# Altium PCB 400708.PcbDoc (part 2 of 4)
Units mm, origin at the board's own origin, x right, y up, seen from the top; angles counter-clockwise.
Board outline 117 x 63.5 mm, 4 copper layers (Top Layer, Mid-Layer 1, Mid-Layer 2, Bottom Layer), stack 1.556 mm thick; 207 components, 162 nets, 822 pads, 1266 vias.
Unrouted connection lines stored in the file: 43.
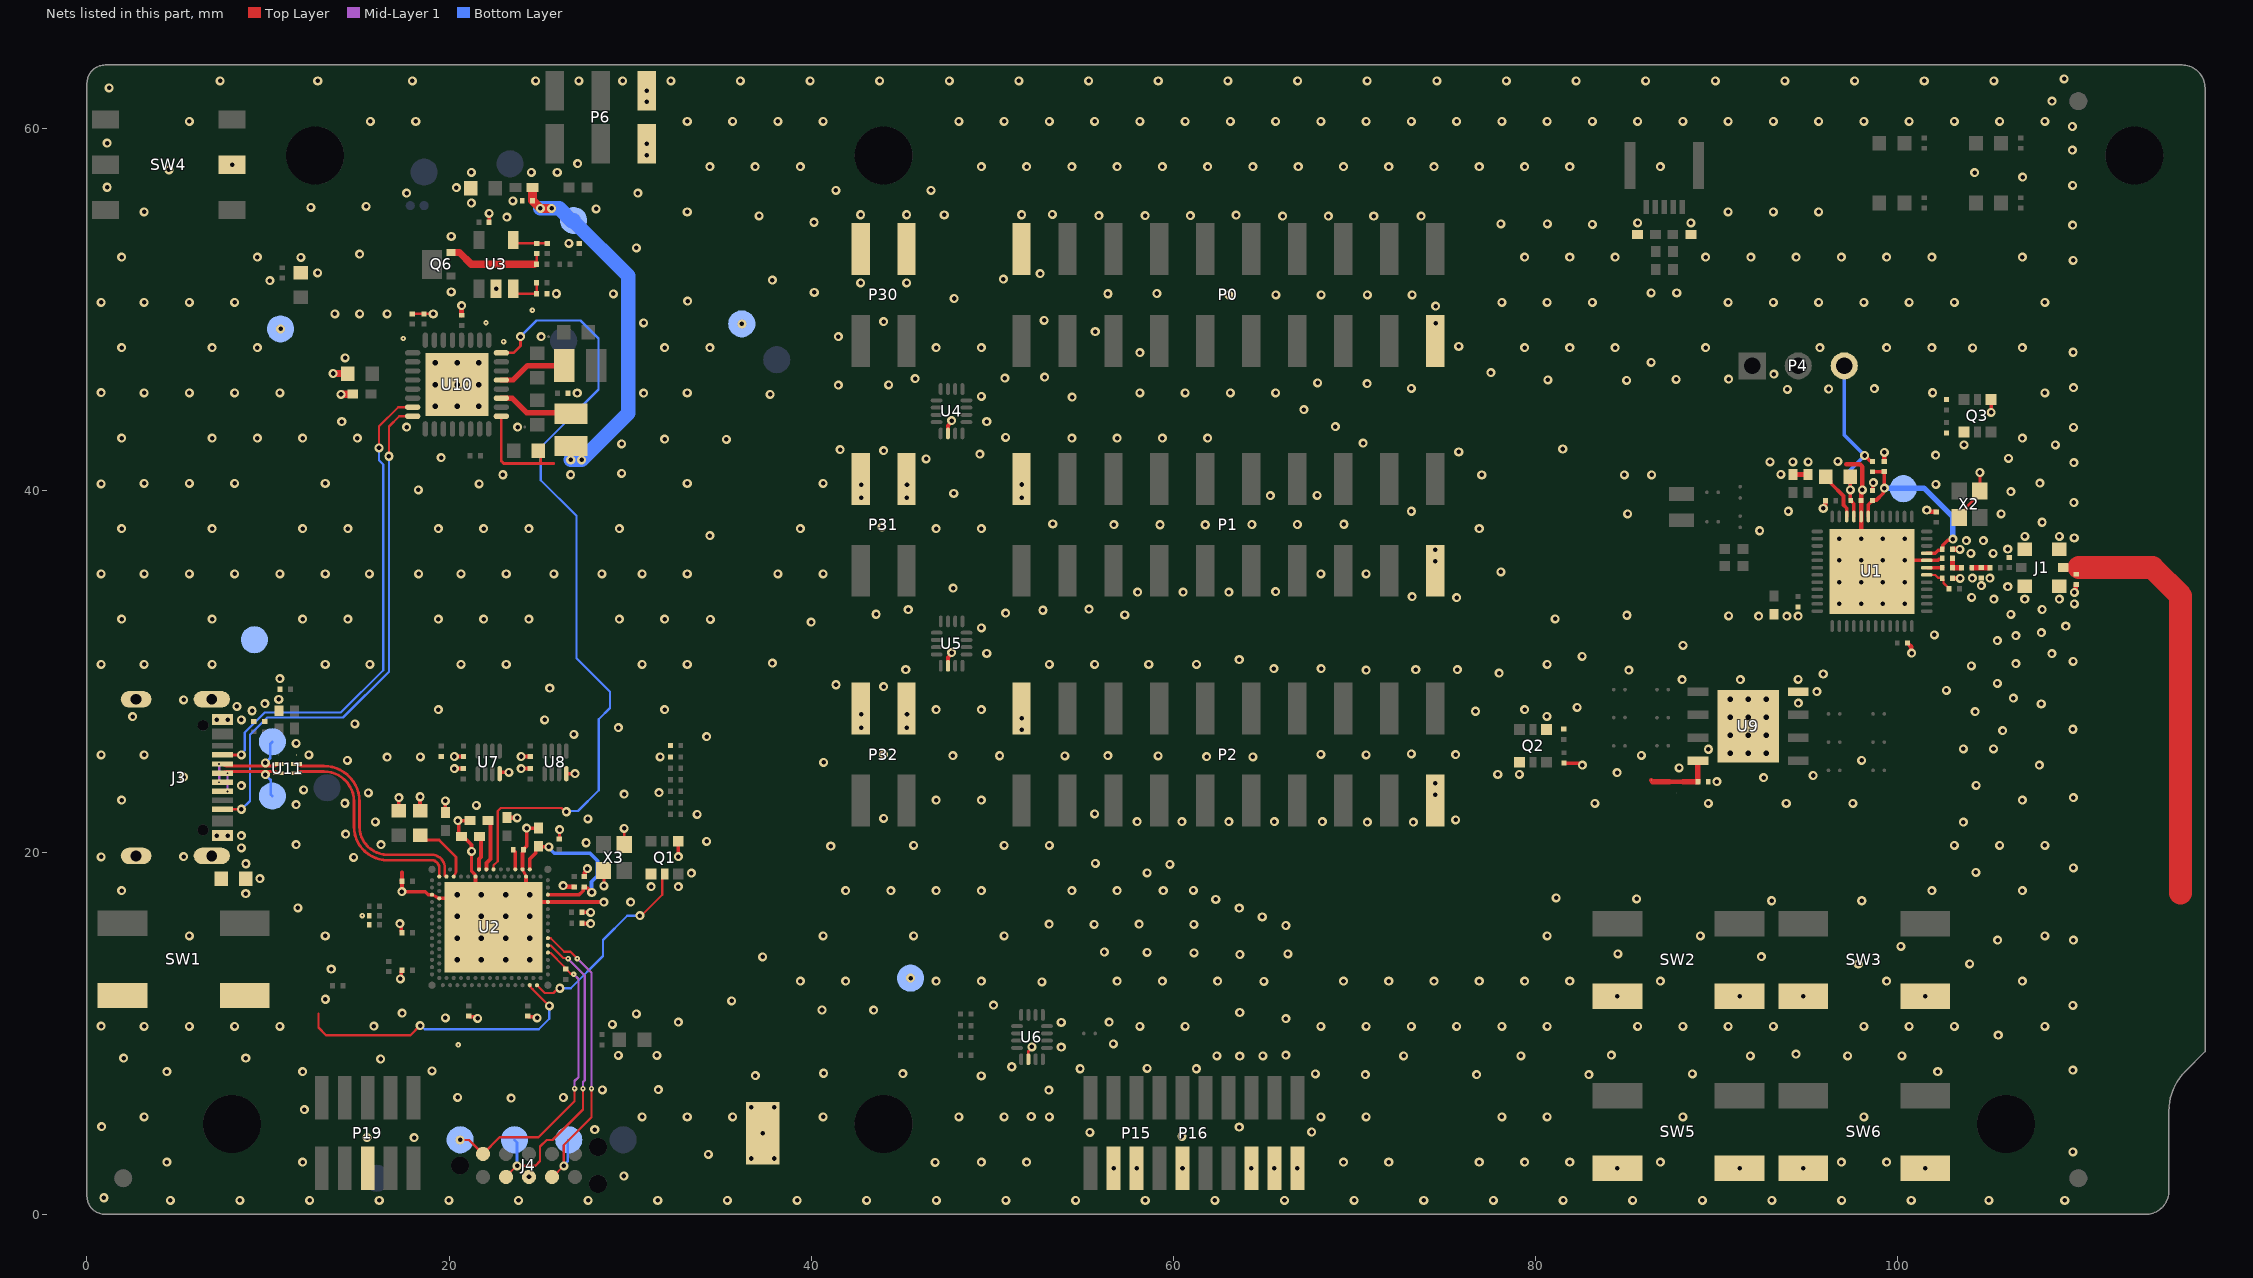
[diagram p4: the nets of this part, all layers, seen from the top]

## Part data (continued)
C42 C43 C54 C58: library part C0603-4µ7-10V-X7S, "Capacitor, X7S, ±10%, 10V", Manufacturer=N.A., Part number IPS=00000001779, Part number NEMS=100200351, Supplier Part Number 1=445-14258-1-ND
C47: library part C0402-1µ0-16V-X5R, "Capacitor, Ceramic, X5R, ±10%, 16V", Manufacturer=Murata, Manufacturer Part Number=GRT155R61C105KE01D, Part number IPS=N.A., Part number NEMS=100200452, Supplier Part Number 1=490-12255-1-ND
C51: library part C0201-TBD, "Chip Cap 0201", Manufacturer=N.A., Part number NEMS=100200002
C59: library part C0603-10n-100V-X7R, "Capacitor, X7R, ±10%, 100V", Manufacturer=Murata, Manufacturer Part Number=GCM188R72A103KA37D, Part number IPS=N.A., Part number NEMS=100200349, Supplier Part Number 1=490-4781-1-ND
C60: library part C0201-3.9p-HQ-Murata, "Capacitor, NP0, ±0.05pF, 25V", Manufacturer=Murata, Manufacturer Part Number=GJM0333C1E3R9WB01, Part number IPS=N.A., Part number NEMS=100200424
C61: library part C0201-0.3p-50V-GRM0335C1HR30BA01, "Capacitor, C0G, ±0.1pF, 50V", Manufacturer=Murata, Manufacturer Part Number=GRM0335C1HR30BA01, Part number IPS=N.A., Part number NEMS=100200650, Supplier Part Number 1=490-6135-2-ND
FB1: library part FB0201-120R@100M-200mA-BLM03AG121SN1D, "Ferrite Bead, 120 Ohm @ 100MHz, 200mA, 500 mOhm Max", Manufacturer=Murata, Manufacturer Part Number=BLM03AG121SN1D, Part number IPS=N.A., Part number NEMS=100300419, Supplier Part Number 1=490-5622-1-ND
FB2 FB3: library part FB0402-120R@100M-500mA, "Ferrite Bead, 120 Ohm @ 100MHz, 500mA, 250 mOhm Max", Manufacturer=Murata, Manufacturer Part Number=BLM15AG121SN1D, Part number IPS=00000009954, Part number NEMS=100300099, Part number Norautron=265230631, Supplier Part Number 1=490-1005-1-ND
Fid1 Fid2 Fid3: library part Fid-Mark, "Fiducial Mark", Manufacturer=N.A., Part number NEMS=100500073
J1: "Coaxial Connector with Switch", Manufacturer=Murata, Part number IPS=00000009955, Part number NEMS=100500400, Part number Norautron=26030338, Supplier Part Number 1=490-4981-1-ND
J3: library part SD-80259-1021, "USB-C Receptacle, 16 Pin, USB 2.0", Manufacturer="Bellweather Electronic Corp.", Part number IPS=N.A., Part number NEMS=100500830
J4: library part TC2050-IDC-NLFP, "CBL PLUG-OF-NAILS 10-PIN", Manufacturer="Tag-Connect LLC", Part number IPS=N.A., Part number NEMS=100500463, Supplier Part Number 1=TC2050-IDC-NL-ND
J7: library part FPC_05P-0.5mm-RA-SMD, "0.5mm FPC, 5P,Right Angle SMT,Double Contact,H=1.2mm,White, Tin plated", Manufacturer=WCON, Manufacturer Part Number=5141-05RZDNWR03, Part number IPS=N.A., Part number NEMS=100500528
JP1: library part "SHUNT JUMPER 2.54mm Black Vertical", "Shunt Jumper 2.54mm Black, open top", Manufacturer=WCON, Manufacturer Part Number=3710-6001OS0B05, Part number IPS=N.A., Part number NEMS=100500728
L1: library part L0603-4µ7-MLZ1608M4R7WT000, "Inductor, 120mA, ±20%, 0.65R", Manufacturer="TDK Corporation", Manufacturer Part Number=MLZ1608M4R7WT000, Part number IPS=N.A., Part number NEMS=100300440, Supplier Part Number 1=445-6390-2-ND
L2: library part L0201-2n7-HQ-Murata, "Inductor, 600mA, ±0.1ｎH, 120mOhm", Manufacturer=Murata, Manufacturer Part Number=LQP03HQ2N7B02, Part number IPS=00000001753, Part number NEMS=100300214, Part number Norautron=N.A., Supplier Part Number 1=490-13909-1-ND
L3 L4: library part L0201-3n5-HQ-Murata, "Inductor, 500mA, ±0.1ｎH, 170mOhm", Manufacturer=Murata, Manufacturer Part Number=LQP03HQ3N5B02, Part number IPS=N.A., Part number NEMS=100300222, Supplier Part Number 1=490-13925-1-ND
L8 L9: library part L0806-2µ2-2500mA-73mOhm-CIGT201610EH2R2MNE, "Inductor, Irms=2.5A, Isat=2.9A, ±20%, DCR=73mΩ", Manufacturer="Samsung Electro-Mechanics America", Manufacturer Part Number=CIGT201610EH2R2MNE, Part number IPS=N.A., Part number NEMS=100300400, Part number Norautron=26521789, Supplier Part Number 1=1276-6901-1-ND
LABEL1: library part Label_12x12, "PCA version label, stick-on, 12x12mm", Manufacturer="Ellco Etikett", Manufacturer Part Number=A33512‐01, Part number IPS=N.A., Part number NEMS=101200028
LD1 LD2 LD3 LD4 LD5: library part "VS 25C7M5", "LED, Green, 0603, 573nm, Vf=2.0V, 24mcd, - 40 to +85°C", Manufacturer="Victory Electronics", Part number IPS="00000001274, 00000009961", Part number NEMS=101400097, Part number Norautron=26313411, Supplier Part Number 1=N.A.
LOGO1: library part "Nordic Logo lying", "Nordic logo lying", Manufacturer=N.A., Part number NEMS=101100001
LOGO2: library part "WEEE Symbol 3x4.5mm", "WEEE Directive symbol", Manufacturer=N.A., Part number NEMS=101100006
LOGO3: "Segger logo, small size", Manufacturer=N.A., Part number NEMS=101100004
NT2 NT3: library part "2 pin starpoint", "Starpoint", Manufacturer=N.A., Part number NEMS=100500603
NT4: library part "2 pin starpoint 20mil", "Starpoint", Part number NEMS=100500717
P0 P1 P2: library part "Pin Header 2x10 SMD, 2.54mm", "Pin Header 2x10, 2.54mm (100mil) SMD", Manufacturer=WCON, Manufacturer Part Number=1125-1210S0M116CR09, Part number IPS=N.A., Part number NEMS=100500738
P4: "Pin List 1x3, 2.54mm (100mil)", Manufacturer=N.A., Part number NEMS=100500304
P6: library part "Pin List 1x3 SMD", "Pin List 1x3, 2.54mm (100mil), SMD", Manufacturer=WCON, Manufacturer Part Number=1125-1103S0M116CR04, Part number IPS=N.A., Part number NEMS=100500306, Part number Norautron=26470016
P15 P19: library part "Pin Header 2x5 SMD, 1.27mm, KS", "Pin Header 2x5, 1.27mm (50mil), SMD, Keying Shroud", Manufacturer=WCON, Manufacturer Part Number=3132-10MS0BK00R5, Part number IPS=N.A., Part number NEMS=100500261
P16: library part "Pin Header 2x10 SMD, 1.27mm, KS, N.C.", "Pin Header 2x10, 1.27mm (50mil), SMD, Keying Shroud", Manufacturer=WCON, Manufacturer Part Number=3132-20MS0BK00R1, Part number IPS=N.A., Part number NEMS=100500279
P30 P31 P32: "Pin Header 2x2, SMD, 2.54mm (100mil)", Manufacturer=WCON, Manufacturer Part Number=1125-1202S0M116CR03, Part number IPS=N.A., Part number NEMS=100500770
Q1 Q2 Q3: "MOSFET 2N-CH 60V 0.17A TSSOP6 (SOT363)", Manufacturer=Nexperia, Manufacturer Part Number=NX138AKSX, Part number IPS=N.A., Part number NEMS=101300207, Supplier Part Number 1=1727-2732-2-ND
Q6: library part PBSS4330PA,115, "30V, 3A, 2.1W, G=270, NPN Transistor", Manufacturer=Nexperia, Part number IPS=N.A., Part number NEMS=101300184, Supplier Part Number 1=1727-5112-1-ND‎
R1 R2 R19 R20: library part R0201-220, "Resistor, ±1%, 0.05W", Manufacturer=N.A., Part number IPS=00000000863, Part number NEMS=100100032, Part number Norautron=26107014
R3 R31 R32 R35 R54: library part R0201-0R, "Resistor, ±5%, 0.05W", Manufacturer=N.A., Part number IPS=00000003245, Part number NEMS=100100001
R4 R9 R37 R38: library part R0201-150, "Resistor, ±1%, 0.05W", Manufacturer=N.A., Part number IPS=00000001420, Part number NEMS=100100029
R5: library part R0201-560, "Resistor, ±1%, 0.05W", Manufacturer=N.A., Part number NEMS=100100038
R6 R8 R13 R14 R15 R16 R17 R23 R55 R56: library part R0201-100k, "Resistor, ±1%, 0.05W", Manufacturer=N.A., Part number IPS=00000001419, Part number NEMS=100100080, Part number Norautron=26108487
R7: library part R0201-47R, "Resistor, ±1%, 0.05W", Manufacturer=N.A., Part number IPS=00000004794, Part number NEMS=100100022, Part number Norautron=26108300
R10 R11 R12 R18 R27: library part R0201-1M0, "Resistor, ±1%, 0.05W", Manufacturer=N.A., Part number IPS=00000001418, Part number NEMS=100100093, Part number Norautron=26107108
R21 R22 R33 R34: library part R0402-0R, "Resistor, ±5%, 0.063W", Manufacturer=N.A., Part number IPS=00000007128, Part number NEMS=100100109, Supplier Part Number 1=146-9661
R24: library part R0402-TBD, "Chip Res 0402", Manufacturer=N.A., Part number NEMS=100100282
R25: library part R0201-270k, "Resistor, ±1%, 0.05W", Manufacturer=N.A., Part number IPS=00000004317, Part number NEMS=100100086
R26: library part R0201-47k, "Resistor, ±1%, 0.05W", Manufacturer=N.A., Part number IPS=00000001423, Part number NEMS=100100076
R28: library part R0201-33k, "Resistor, ±1%, 0.05W", Manufacturer=N.A., Part number IPS=00000001708, Part number NEMS=100100073
R29 R30: library part R0201-18k, "Resistor, ±1%, 0.05W", Manufacturer=N.A., Part number IPS=00000001707, Part number NEMS=100100069
R36: library part R0201-1k0, "Resistor, ±1%, 0.05W", Manufacturer=N.A., Part number IPS=00000005786, Part number NEMS=100100043
SB1 SB8 SB10: Manufacturer=N.A., Part number NEMS=100500458
SB2 SB9: library part "Solderbridge Shorted", "Shorted Solderbridge", Manufacturer=N.A., Part number NEMS=100500459
SB3 SB4 SB11 SB12 SB13 SB14 SB15 SB16 SB24: library part "Solderbridge Shorted 0.4mm", "Shorted Solderbridge", Manufacturer=N.A., Part number NEMS=100500561
SB5 SB6 SB17 SB18 SB19 SB20 SB21 SB22: library part "Solderbridge 0.4mm", Manufacturer=N.A., Part number NEMS=100500560
SW1 SW2 SW3 SW5 SW6: library part Switch-PB-6.2x6.3mm-SMD, "Tactile Switch, SPNO, SMD, 160gf, 6.2x6.3x2.5mm", Manufacturer=Dailywell, Manufacturer Part Number=TS604VM1-025BR-R, Part number IPS=00000007812, Part number NEMS="101500001, 101500133", Part number Norautron=N.A.
SW4: "Slide Switch DPDT", Manufacturer="HUA-JIE CORP.", Part number IPS=N.A., Part number NEMS=101500131
TP1 TP2 TP3 TP4 TP5 TP6 TP7 TP8 TP9 TP10 TP11 TP12 TP13 TP14 TP15 TP16 TP17 TP18: library part TP_SMD_Ø1.5MM, "1.5mm circular SMD testpad", Manufacturer="Nordic Semiconductor", Manufacturer Part Number=N.A., Part number NEMS=100500477
TP22: library part "TP - S1751-46R", "PC TEST POINT TIN SMD L", Manufacturer=Harwin, Manufacturer Part Number=S1751-46R, Part number IPS=N.A., Part number NEMS=100500525, Supplier Part Number 1=952-1478-1-ND
U1: "Multi-protocol Bluetooth Low Energy, IEEE 802.15.4 and 2.4GHz proprietary Wireless MCU", Manufacturer="Nordic Semiconductor", Part number IPS=N.A., Part number NEMS=102000382
U2: library part nRF5340-QKAAD0, "Multi-protocol Bluetooth Low Energy, IEEE 802.15.4, ANT and 2.4GHz proprietary system-on-chip", Manufacturer="Nordic Semiconductor", Part number IPS=N.A., Part number NEMS=102000216, Part number Norautron=NOD26470035
U3: library part TLV271CW5-7, "Dual rail to rail CMOS Amplifier", Manufacturer="Diodes Incorporated", Part number IPS=N.A., Part number NEMS=101900398, Supplier Part Number 1=TLV271CW5-7DICT-ND
U4 U5 U6: "Data / Audio Low-Voltage Dual DPDT Analog Switch", Manufacturer="ON Semiconductor", Part number IPS=00000009986, Part number NEMS=101900422, Part number Norautron=26500608, Supplier Part Number 1=FSA2466UMXCT-ND
U7 U8: library part TXB0302DQMR, "2-bit bidirectional voltage-level translator with automatic direction sensing", Manufacturer="Texas Instruments", Part number IPS=N.A., Part number NEMS=101900198, Supplier Part Number 1=296-36871-1-ND
U9: library part MX25R6435FZNIL0, "Ultra low power, 64M-bit, serial multi I/O flash memory", Manufacturer=Macronix, Part number IPS=00000004370, Part number NEMS=101900438, Part number Norautron=N.A.
U10: "Li-Ion/Li-Polymer USB-C battery charger with high efficiency buck regulators, LDOs or load switches, LED drivers, TWI and VBUSOUT", Manufacturer="Nordic Semiconductor", Part number IPS=N.A., Part number NEMS=102000306
U11: "2 Line Common mode filter with ESD protection for USB 2.0 interface", Manufacturer=STMicroelectronics, Part number IPS=N.A., Part number NEMS=100800034, Supplier Part Number 1=497-13420-2-ND
X1: library part XTAL_SMD2012_32.768kHz_9pF_TXC, "XTAL SMD 2012, 32.768kHz, 9pF, ±20ppm", Manufacturer="TXC Corporation", Manufacturer Part Number=9HT11-32.768KDZC-T, Part number IPS=N.A., Part number NEMS=101600107, Supplier Part Number 1=887-1426-2-ND
X2 X3: library part XTAL_SMD2016_32MHz_8pF_Golledge, "XTAL SMD 2016, 32MHz, Cl=8pF, Tol: ±10ppm, Stab: ±15ppm", Manufacturer=Golledge, Manufacturer Part Number=MP06003, Part number IPS=00000001431, Part number NEMS=101600041, Part number Norautron=N.A.

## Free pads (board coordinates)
  round 3.2 hole 3.2 unplated: 1(8.004,5) 1(12.604,58.5) 1(44.004,5) 1(44.004,58.5) 1(106.004,5) 1(113.104,58.5)

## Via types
v1: diameter 0.5, hole 0.25, Top Layer to Bottom Layer, tented both sides, 1159 vias
v2: diameter 0.3, hole 0.1, Top Layer to Mid-Layer 1, tented top, 61 vias
v3: diameter 0.61, hole 0.305, Top Layer to Bottom Layer, tented both sides, 28 vias
v4: diameter 0.61, hole 0.305, Top Layer to Bottom Layer, 9 vias
v5: diameter 0.3, hole 0.1, Top Layer to Mid-Layer 1, tented both sides, 9 vias

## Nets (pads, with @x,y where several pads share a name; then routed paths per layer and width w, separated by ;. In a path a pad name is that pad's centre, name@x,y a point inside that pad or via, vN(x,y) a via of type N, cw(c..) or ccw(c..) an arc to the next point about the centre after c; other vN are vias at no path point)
ANT: C40.2 J1.3 | length 22.7
  Top Layer w1.27: 110.033,35.73 114.1,35.73 115.66,34.171 115.66,17.748
DBGR'_N: J3.A7 J3.B7 TP17.1 U11.2 | length 5.5
  Top Layer w0.153: J3.B7@7.489,24.875 ccw(c7.727,25.113) 7.727,24.776 10.322,24.776 ccw(c10.322,25.141) U11.2@10.579,24.883
  Mid-Layer 1 w0.127: v2(7.3,23.881) v2(7.3,24.884)
  Bottom Layer w0.153: v1(9.85,24.95) 10.125,25.225 10.125,26 TP17.1@10.24,26.115
DBGR'_P: J3.A6 J3.B6 TP18.1 U11.3 | length 5.5
  Top Layer w0.153: J3.A6@7.489,24.375 cw(c7.727,24.137) 7.727,24.473 10.361,24.473 cw(c10.361,24.165) U11.3@10.579,24.383
  Mid-Layer 1 w0.127: v2(7.763,23.371) v2(7.763,24.374)
  Bottom Layer w0.153: v1(9.85,24.3) 10.147,24.003 10.147,23.206 TP18.1@10.24,23.113
DBGR_BUTTON: SB2.2 U2.AL27 | length 16.5
  Top Layer w0.125: SB2.2@12.788,11.089 12.788,10.325 13.207,9.906 17.872,9.906 v1(18.4,10.434) ; U2.AL27@24.46,12.664 24.46,12.637 24.51,12.587 24.51,12.555 24.631,12.434 24.631,12.427 v1(25.54,11.518)
  Top Layer w0.15: U2.AL27@24.46,12.622 U2.AL27@24.46,12.637
  Bottom Layer w0.125: v1(18.4,10.434) 18.456,10.434 18.661,10.229 24.956,10.229 25.54,10.813 v1(25.54,11.518)
DBGR_LED: Q1.2 U2.AL29 | length 11.1
  Top Layer w0.125: U2.AL29@24.86,12.664 25.285,12.24 25.767,12.24 26.023,12.496 v1(26.124,12.496) ; v1(30.539,16.505) 30.617,16.505 31.777,17.665 31.777,18.677 Q1.2@31.915,18.815
  Bottom Layer w0.125: v1(26.124,12.496) 26.719,12.496 28.5,14.278 28.5,15.163 29.842,16.505 v1(30.539,16.505)
DBGR_N: U2.B4 U11.7 | length 12.6
  Top Layer w0.153: U11.7@11.579,24.883 ccw(c11.833,25.137) 11.833,24.778 11.879,24.778 13.05,24.778 13.084,24.778 cw(c13.084,22.81) 15.053,22.81 15.053,21.422 ccw(c16.6,21.422) 16.6,19.875 19.033,19.875 cw(c19.033,19.138) 19.77,19.138 19.77,18.755 ccw(c19.86,18.755) U2.B4@19.86,18.664
DBGR_P: U2.B2 U11.6 | length 12
  Top Layer w0.153: U11.6@11.579,24.383 cw(c11.801,24.161) 11.801,24.475 11.879,24.475 13.05,24.475 13.084,24.475 cw(c13.084,22.81) 14.75,22.81 14.75,21.422 ccw(c16.6,21.422) 16.6,19.572 19.033,19.572 cw(c19.033,19.138) 19.467,19.138 19.467,18.664 U2.B2@19.46,18.664
DBGR_RESET: J4.10 R6.1 TP4.1 U2.AC31 | length 17
  Top Layer w0.125: v1(20.616,4.115) 21.107,4.115 J4.10@21.878,3.344 22.795,4.261 24.943,4.261 26.934,6.253 v5(26.934,6.955) ; U2.AC31@25.46,14.464 25.479,14.445 25.616,14.445 26.372,13.689 26.372,13.628 26.445,13.556 R6.1@26.46,13.556 26.475,13.556 26.726,13.304 26.857,13.304 v2(26.89,13.271)
  Mid-Layer 1 w0.125: v2(26.89,13.271) 27.15,13.011 27.15,7.583 26.934,7.368 v5(26.934,6.955)
DBGR_SWDCLK: J4.4 TP6.1 U2.W31 | length 16.9
  Top Layer w0.125: U2.W31@25.46,15.264 25.471,15.254 25.624,15.254 26.363,14.515 26.71,14.515 27.087,14.139 v2(27.087,14.134) ; J4.4@25.688,2.074 25.724,2.074 v1(26.34,2.69) 26.34,3.836 27.873,5.369 v5(27.873,6.955)
  Mid-Layer 1 w0.125: v2(27.087,14.134) 27.873,13.348 v5(27.873,6.955)
  Bottom Layer w0.15: v1(26.34,2.69) 26.34,2.729 26.564,2.953 26.564,4.062 TP6.1@26.616,4.115
DBGR_SWDIO: J4.2 TP5.1 U2.AA31 | length 17.9
  Top Layer w0.125: J4.2@23.148,2.074 23.148,2.099 23.74,2.69 v1(23.759,2.69) 24.771,2.69 25.032,2.95 25.032,3.75 25.396,4.115 25.719,4.115 27.401,5.796 v5(27.401,6.95) ; U2.AA31@25.46,14.864 25.471,14.854 25.624,14.854 26.312,14.166 26.547,14.166 v2(26.579,14.134)
  Mid-Layer 1 w0.125: v2(26.579,14.134) 26.579,14.13 27.504,13.205 27.504,7.414 27.401,7.311 v5(27.401,6.95)
  Bottom Layer w0.15: TP5.1@23.616,4.115 23.759,3.972 v1(23.759,2.69)
DCC: L1.2 U1.46 | length 2.7
  Top Layer w0.2: L1.2@96.053,40.809 96.328,40.534 96.328,40.396 97.033,39.691 97.033,39.186 97.205,39.014 U1.46@97.205,38.555
DECD: C1.2 FB1.1 L1.1 P4.3 U1.45 | length 10.6
  Top Layer w0.2: L1.1@97.414,40.798 v1(97.414,40.022) 97.414,39.46 C1.2@97.435,39.439 97.435,39.424 97.47,39.389 97.485,39.389 97.605,39.269 97.605,38.78 U1.45@97.605,38.555 ; v1(98.201,41.927) 98.491,41.637 FB1.1@98.649,41.637
  Bottom Layer w0.2: P4.3@97.075,46.88 97.075,43.053 v1(98.201,41.927) 97.414,41.139 v1(97.414,40.022)
DECRF: C2.2 C5.2 C12.1 FB1.2 TP2.1 U1.33 U1.43 | length 11.2
  Top Layer w0.2: U1.43@98.405,38.555 98.405,39.204 C12.1@98.633,39.432 98.668,39.467 98.856,39.467 99.236,39.847 99.236,40.066 v1(99.294,40.123) C2.2@99.294,41.032 FB1.2@98.633,41.032 ; U1.33@101.63,36.53 102.093,36.53 102.263,36.7 102.453,36.7 102.488,36.735 102.488,36.745 102.523,36.78 102.523,36.975 102.795,37.246 103.021,37.246 v1(103.078,37.304)
  Bottom Layer w0.15: TP2.1@100.252,40.123 TP2.1@100.273,40.144
  Bottom Layer w0.3: v1(99.294,40.123) 101.478,40.123 103.078,38.523 v1(103.078,37.304)
GND: C1.1 C2.1 C3.1 C4.2 C5.1 C6.1 C7.2 C8.2 C9.1 C10.1 C11.2 C12.2 C13.2 C14.2 C15.1 C16.2 C17.2 C18.2 C19.1 C20.2 C21.2 C22.2 C23.1 C26.1 C29.2 C30.2 C31.2 C32.1 C33.2 C34.2 C35.2 C36.2 C37.2 C38.1 C39.1 C40.1 C41.1 C42.2 C43.2 C44.2 C45.1 C46.1 C47.1 C48.1 C49.2 C50.2 C52.2 C53.1 C54.2 C55.2 C56.1 C57.1 C58.2 C59.2 C60.2 C61.1 J1.2 J3.A1 J3.A12 J4.3 NT2.1 NT3.1 P0.2 P0.19 P1.2 P1.19 P2.2 P2.19 P6.1 P15.3 P15.5 P15.9 P16.3 P16.5 P16.9 P16.15 P16.17 P16.19 P19.5 P30.2 P30.4 P31.2 P31.4 P32.2 P32.4 Q1.1 Q1.4 Q2.1 Q2.4 Q3.1 Q3.4 R7.2 R10.2 R11.2 R12.2 R18.1 R25.2 R26.2 R27.2 R30.1 R55.2 R56.2 SW1.1 SW2.1 SW3.1 SW4.5 SW5.1 SW6.1 TP12.1 TP13.1 TP14.1 TP15.1 TP22.1 U1.32 U1.44 U1.49 U2.104 U2.A25 U2.B12 U2.B26 U2.G1 U2.H2 U2.J31 U3.2 U4.6 U5.6 U6.6 U7.4 U8.4 U9.4 U9.9 U10.33 U11.5 U11.8 X2.2 X2.4 X3.2 X3.4 | length 57.6
  Top Layer w0.15: R26.2@17.981,49.761 18.619,49.761 18.627,49.753 v1(19.128,49.753) ; C37.2@26.096,20.744 26.103,20.751 26.103,21.258 v1(26.11,21.265) ; X3.4@28.534,18.99 28.56,18.965 v1(28.56,18.147) ; X3.2@29.677,20.448 v1(29.677,21.323) ; U6.6@52.004,8.575 52.004,9.001 52.201,9.197 v1(52.201,9.264) ; X2.4@103.418,38.509 103.768,38.859 103.768,39.026 104.218,39.476 104.218,39.609 X2.2@104.568,39.959 ; X2.2@104.568,39.934 X2.2@104.568,39.959 ; v1(104.568,40.987) X2.2@104.568,39.959
  Top Layer w0.165: U2.A25@24.06,19.064 U2.B26@24.26,18.664
  Top Layer w0.187: U2.G1@19.06,17.664 U2.H2@19.46,17.464 U2.104@20.16,17.464 ; v1(21.245,20.052) 21.245,18.96 21.453,18.752 21.453,18.672 U2.B12@21.46,18.664
  Top Layer w0.188: v1(17.394,17.834) 18.688,17.834 18.85,17.672 19.053,17.672 U2.G1@19.06,17.664
  Top Layer w0.2: C42.2@17.231,22.302 v1(17.231,23.024) ; v1(17.282,16.065) 17.282,15.983 17.369,15.897 17.369,15.608 C18.2@17.404,15.573 ; v1(17.308,13.017) 17.365,13.074 17.365,13.436 C20.2@17.428,13.499 ; C13.2@17.369,18.436 C13.2@17.404,18.401 ; v1(17.394,17.834) 17.404,17.844 C13.2@17.404,18.401 ; 17.404,18.899 C13.2@17.404,18.401 ; C43.2@18.4,22.302 v1(18.4,23.075) ; C38.1@19.797,22.203 v1(19.797,22.846) ; v1(20.298,24.634) C53.1@20.798,24.634 ; v1(20.298,25.299) C14.2@20.798,25.3 ; v1(20.488,21.756) v1@20.508,21.756 ; C45.1@20.694,20.891 20.679,20.891 20.529,21.041 20.529,21.735 v1@20.508,21.756 ; C45.1@20.719,20.916 20.894,20.741 20.932,20.741 21.243,20.429 21.243,20.054 v1(21.245,20.052) ; C22.2@21.092,10.954 21.127,10.919 21.407,10.919 21.494,10.832 v1(21.575,10.832) ; C39.1@21.262,21.756 v1@20.508,21.756 ; C49.2@22.219,54.811 v1(22.219,55.305) ; U7.4@22.795,24.349 22.795,24.398 22.818,24.421 v1(23.308,24.421) ; v1@23.981,24.634 C15.1@24.481,24.634 ; v1(23.981,25.299) C16.2@24.481,25.3 ; U2.A25@24.06,19.064 24.06,19.987 24.085,20.012 24.085,20.134 24.285,20.334 v1(24.285,21.34) C32.1@24.953,21.34 ; C34.2@24.343,10.954 24.378,10.919 24.728,10.919 24.788,10.858 v1(24.87,10.858) ; U8.4@26.478,24.349 v1(26.96,24.349) ; v1(32.665,19.764) Q1.4@32.665,20.615 ; U5.6@47.564,30.311 47.564,30.765 47.76,30.961 v1(47.76,31.042) ; U4.6@47.564,43.125 47.564,43.579 47.76,43.775 v1(47.76,43.856) ; R12.2@81.607,24.936 82.412,24.936 82.523,24.825 v1(82.604,24.825) ; C12.2@98.633,40.002 98.659,40.027 98.659,40.403 v1(98.684,40.428) ; U1.49@100.443,36.13 102.233,36.13 102.303,36.2 102.453,36.2 102.488,36.235 C6.1@102.488,36.25 ; v1(105.185,44.314) Q3.1@105.185,45.03
  Top Layer w0.203: R7.2@27.345,16.687 v1(27.823,16.687) ; C35.2@27.353,16.078 27.36,16.071 27.816,16.071 v1(27.823,16.064)
  Top Layer w0.225: U2.104@21.46,17.264 U2.B12@21.46,18.664 ; C31.2@23.15,21.905 C31.2@23.16,21.915 ; C31.2@23.211,21.915 23.751,21.915 v1(23.759,21.907) ; U2.104@23.86,17.264 U2.104@24.26,17.264 ; U2.B26@24.26,18.664 U2.104@24.26,17.264 ; C33.2@27.459,18.661 27.474,18.661 27.496,18.683 27.496,18.879 27.644,19.027 v1(27.644,19.101) ; v1@28.56,17.264 U2.104@24.26,17.264
  Top Layer w0.25: v1(26.299,18.167) 26.367,18.167 26.433,18.101 26.899,18.101 C36.2@26.909,18.091 ; U9.9@91.766,26.971 91.766,27.261 U9.9@93.341,28.836 ; C3.1@94.239,40.877 C10.1@95.077,40.877 ; v1(95.915,39.006) 95.915,39.073 96.027,39.185 96.027,39.427 C11.2@96.037,39.437 ; 97.195,41.453 97.938,41.453 98.074,41.317 98.074,39.954 98.015,39.895 98.015,39.449 C1.1@98.005,39.439 U1.44@98.005,38.555 v1(98.005,37.33) ; C2.1@99.294,41.602 v1(99.294,42.104) ; C8.2@100.569,31.568 100.569,31.553 100.579,31.543 100.594,31.543 100.77,31.367 100.77,31.027 v1(100.792,31.005) ; v1(101.63,38.904) 101.698,38.904 101.784,38.818 102.154,38.818 C4.2@102.164,38.808 ; C60.2@103.058,35.149 103.063,35.144 103.466,35.144 v1(103.471,35.139) ; v1(109.789,34.36) 109.789,34.427 109.855,34.493 109.855,34.785 109.865,34.795 C40.1@109.88,34.795
  Top Layer w0.254: X3.4@28.531,18.994 X3.4@28.534,18.99 ; X3.2@29.677,20.448 X3.2@29.681,20.444
  Top Layer w0.27: C29.2@20.699,49.671 v1(20.699,50.211) ; C19.1@85.652,54.123 C19.1@85.654,54.124 ; v1@85.654,54.779 v1(85.656,54.781)
  Top Layer w0.3: C5.1@103.084,36.75 103.454,36.75 v1(103.459,36.745)
  Top Layer w0.4: v1(13.6,46.456) 14.401,46.456 C26.1@14.404,46.459 ; v1(14.032,45.304) 14.037,45.308 14.679,45.308 C23.1@14.684,45.313
  other v1: 4.604,0.78 8.451,0.78 12.298,0.78 16.145,0.78 19.991,0.78 23.838,0.78 27.685,0.78 31.532,0.78 35.379,0.78 39.225,0.78 43.072,0.78 46.919,0.78 50.766,0.78 54.613,0.78 58.459,0.78 62.306,0.78 66.153,0.78 70,0.78 73.847,0.78 77.693,0.78 81.54,0.78 85.387,0.78 89.234,0.78 93.081,0.78 96.927,0.78 100.774,0.78 105.063,0.78 109.254,0.78 0.929,0.925 24.418,2.074 29.658,2.125 56.708,2.553 57.978,2.553 60.518,2.553 64.328,2.55 65.598,2.55 66.868,2.55 84.543,2.561 91.293,2.561 94.804,2.561 101.554,2.561 4.412,2.887 11.912,2.887 46.85,2.875 49.412,2.887 51.912,2.887 69.412,2.887 71.912,2.887 76.912,2.887 79.412,2.887 81.912,2.887 86.912,2.887 96.912,2.887 99.412,2.887 36.708,3.091 37.972,3.091 34.328,3.323 109.704,3.458 15.479,4.246 18.07,4.246 60.489,4.32 37.323,4.494 55.403,4.531 67.649,4.555 28.05,4.693 0.804,4.85 63.655,4.826 3.162,5.387 30.662,5.387 33.162,5.387 35.662,5.387 40.662,5.387 48.162,5.387 50.662,5.387 53.162,5.387 68.162,5.387 70.662,5.387 78.162,5.387 80.662,5.387 88.162,5.387 98.162,5.387 52.163,5.412 12.01,5.79 36.708,5.916 37.973,5.916 23.433,6.425 20.473,6.468 26.323,6.461 28.47,6.882 53.133,6.866 31.565,6.896 36.919,7.667 49.402,7.657 70.616,7.722 76.765,7.728 82.963,7.722 67.856,7.766 88.689,7.766 45.073,7.779 40.698,7.8 4.412,7.887 11.912,7.887 102.24,7.887 19.06,7.937 109.704,7.975 54.861,8.05 61.288,8.05 58.568,8.069 51.086,8.16 16.224,8.588 2.021,8.637 8.771,8.637 62.419,8.756 63.68,8.747 64.959,8.76 72.729,8.76 91.893,8.76 97.257,8.76 100.261,8.76 29.36,8.784 79.213,8.763 31.481,8.79 66.229,8.798 84.205,8.798 94.409,8.855 53.821,9.246 56.704,9.429 105.582,9.906 3.162,10.387 5.662,10.387 8.162,10.387 10.662,10.387 58.162,10.387 60.662,10.387 68.162,10.387 70.662,10.387 73.162,10.387 75.662,10.387 78.162,10.387 80.662,10.387 85.662,10.387 88.162,10.387 90.662,10.387 93.162,10.387 98.162,10.387 100.662,10.387 103.162,10.387 108.162,10.387 0.78,10.4 15.845,10.4 29.021,10.499 53.821,10.614 32.665,10.623 56.465,10.623 66.229,10.825 19.797,10.858 30.354,11.077 17.404,11.125 63.68,11.158 40.604,11.295 43.458,11.287 109.704,11.55 50.078,11.568 35.61,11.793 13.165,11.889 84.543,12.058 91.293,12.058 94.804,12.061 101.554,12.061 52.754,12.851 65.01,12.877 39.412,12.887 41.912,12.887 46.912,12.887 49.412,12.887 56.912,12.887 59.412,12.887 62.456,12.887 69.412,12.887 71.912,12.887 74.412,12.887 76.912,12.887 79.412,12.887 81.912,12.887 86.912,12.887 99.412,12.887 106.912,12.887 45.496,13.056 13.494,13.556 97.848,13.843 104.002,13.843 37.328,14.227 92.496,14.239 63.689,14.361 66.338,14.393 84.575,14.393 61.153,14.453 56.208,14.5 58.568,14.478 100.205,14.806 105.551,15.15 109.729,15.15 5.662,15.387 13.162,15.387 40.662,15.387 45.662,15.387 50.662,15.387 80.662,15.387 89.122,15.387 108.162,15.387 66.229,15.963 55.631,16.021 53.146,16.043 58.128,16.043 61.149,16.027 64.925,16.443 11.655,16.938 63.655,16.924 28.56,17.258 30.037,17.258 93.059,17.33 98.041,17.33 62.354,17.411 85.608,17.437 81.157,17.487 8.771,17.727 1.912,17.887 41.912,17.887 44.412,17.887 46.912,17.887 49.412,17.887 54.412,17.887 56.912,17.887 59.454,17.889 61.115,17.903 101.913,17.887 106.912,17.887 31.165,18.107 32.665,18.107 9.548,18.552 33.386,18.858 58.568,18.869 104.351,18.9 109.729,19.15 59.819,19.339 8.775,19.375 55.702,19.396 14.734,19.724 0.78,19.754 5.335,19.769 8.529,20.25 41.088,20.346 45.662,20.387 50.662,20.387 53.162,20.387 103.162,20.387 105.662,20.387 108.162,20.387 11.55,20.426 16.242,20.426 27.575,20.535 34.225,20.615 7.168,20.921 7.779,20.925 8.529,20.925 14.292,21.012 15.936,21.684 70.729,21.675 73.275,21.675 103.66,21.679 58.012,21.7 60.489,21.7 63.077,21.7 65.596,21.7 68.25,21.7 75.604,21.8 27.673,21.858 44.004,21.881 33.711,22.098 55.662,22.125 21.51,22.598 11.55,22.644 14.242,22.718 83.304,22.712 89.571,22.712 93.87,22.712 97.547,22.712 1.912,22.887 46.912,22.887 49.412,22.887 106.912,22.887 109.729,23.025 74.484,23.177 29.675,23.225 15.55,23.294 31.6,23.3 11.966,23.455 8.527,23.694 104.354,23.708 74.484,23.828 90.041,23.909 92.626,24.13 5.338,24.165 95.355,24.249 77.934,24.309 79.134,24.308 84.532,24.406 23.981,24.633 87.951,24.671 107.854,24.825 40.698,24.977 14.384,25.086 98.03,25.08 16.581,25.267 18.417,25.273 31.665,25.273 61.85,25.291 64.412,25.28 47.839,25.343 50.413,25.339 54.025,25.331 56.4,25.343 59.175,25.331 85.872,25.36 0.78,25.387 3.162,25.387 12.26,25.387 70.662,25.386 44.004,25.4 68.162,25.411 75.604,25.4 73.162,25.441 89.571,25.699 103.66,25.715 105.32,25.723 11.55,26.025 34.232,26.395 26.899,26.524 105.817,26.731 51.649,26.785 109.71,26.805 42.759,26.888 45.284,26.885 29.356,26.899 14.804,27.1 7.171,27.325 7.779,27.325 8.529,27.325 25.278,27.325 51.649,27.41 2.517,27.497 80.643,27.517 42.759,27.622 45.299,27.622 104.299,27.773 76.704,27.8 9.125,27.825 19.412,27.887 31.912,27.887 46.912,27.887 49.412,27.887 79.412,27.887 82.323,28.009 8.283,28.065 107.957,28.2 9.825,28.225 94.536,28.243 5.335,28.423 10.596,28.452 106.422,28.522 95.557,28.881 102.714,28.946 25.565,29.071 44.004,29.161 41.377,29.263 105.53,29.333 88.123,29.54 91.335,29.54 94.529,29.556 10.662,29.6 95.915,29.857 78.004,29.9 45.23,30.096 70.662,30.073 85.173,30.073 73.404,30.1 75.704,30.1 65.57,30.15 68.178,30.15 104.094,30.305 0.78,30.387 3.162,30.387 6.919,30.387 13.162,30.387 15.628,30.387 20.662,30.387 23.162,30.387 30.662,30.387 33.162,30.387 53.162,30.387 55.662,30.387 58.655,30.387 61.292,30.387 80.662,30.387 106.555,30.43 37.86,30.462 109.722,30.556 63.655,30.645 82.599,30.83 108.542,30.981 49.704,31 88.166,31.441 105.53,31.705 106.555,31.98 102.05,32.022 107.96,32.137 49.404,32.4 109.311,32.503 40,32.725 1.912,32.887 6.912,32.887 11.912,32.887 14.412,32.887 19.412,32.887 21.912,32.887 24.412,32.887 29.412,32.887 31.912,32.887 34.434,32.872 81.104,32.9 90.69,33.062 92.34,33.055 93.905,33.055 94.53,33.055 85.068,33.102 57.329,33.125 43.593,33.158 106.275,33.15 50.748,33.216 52.802,33.378 45.369,33.418 108.005,33.42 55.353,33.438 96.805,33.73 98.005,33.73 99.205,33.73 100.405,33.73 109.788,33.73 105.34,33.989 107.045,33.989 108.955,33.989 75.657,34.081 104.115,34.093 73.204,34.127 58.043,34.375 60.552,34.375 63.079,34.375 65.657,34.406 47.842,34.598 106.107,34.685 104.646,34.736 96.805,34.93 98.005,34.93 99.205,34.93 100.405,34.93 104.149,35.154 105.121,35.154 0.78,35.387 3.162,35.387 5.662,35.387 8.162,35.387 10.662,35.387 13.162,35.387 15.601,35.387 18.326,35.387 20.662,35.387 23.162,35.387 25.792,35.387 28.449,35.387 30.662,35.387 33.162,35.387 38.162,35.387 40.662,35.387 68.162,35.387 70.662,35.387 78.104,35.5 74.475,36.074 96.805,36.13 98.005,36.13 99.205,36.13 100.405,36.13 104.068,36.525 105.3,36.525 74.475,36.725 106.107,36.755 103.825,37.225 104.758,37.225 96.805,37.33 99.205,37.33 100.405,37.33 109.78,37.38 107.055,37.456 108.955,37.456 34.412,37.5 92.399,37.77 1.912,37.887 6.912,37.887 11.912,37.887 14.412,37.887 19.412,37.887 21.912,37.887 24.412,37.887 29.412,37.887 39.412,37.887 46.912,37.887 49.412,37.887 76.912,37.887 43.93,37.974 56.729,38.107 59.275,38.1 61.775,38.1 64.352,38.115 66.864,38.115 53.35,38.15 69.429,38.127 108.005,38.238 85.104,38.7 105.741,38.7 73.162,38.846 93.984,38.846 109.76,39.33 42.759,39.588 45.284,39.585 51.629,39.585 65.374,39.716 67.95,39.721 47.883,39.829 106.277,39.93 18.313,40.025 98.074,40.022 42.759,40.322 45.299,40.322 51.65,40.325 102.135,40.33 0.78,40.355 21.668,40.355 3.162,40.387 5.662,40.387 8.162,40.387 13.162,40.387 33.162,40.387 40.662,40.387 107.885,40.405 22.981,40.863 26.719,40.863 77.05,40.855 84.929,40.855 86.438,40.855 93.579,40.885 29.53,40.941 109.76,41.53 92.973,41.571 94.239,41.571 95.077,41.571 96.728,41.596 46.351,41.736 106.148,41.771 19.567,41.808 102.123,41.944 49.32,42.006 75.779,42.131 44.004,42.193 41.604,42.251 81.525,42.286 103.689,42.517 108.736,42.517 29.53,42.568 70.5,42.615 35.318,42.813 31.912,42.835 1.912,42.887 6.912,42.887 9.412,42.887 11.912,42.887 14.943,42.89 54.412,42.887 56.912,42.887 59.412,42.887 61.912,42.887 106.912,42.887 50.748,42.931 109.739,43.48 17.663,43.492 23.792,43.496 68.959,43.525 14.075,43.799 49.704,43.8 67.225,44.461 54.425,45.15 49.403,45.188 37.736,45.303 3.162,45.387 5.662,45.387 8.162,45.387 10.662,45.387 27.084,45.371 30.753,45.371 33.162,45.387 58.162,45.387 60.662,45.387 63.162,45.387 65.662,45.387 108.162,45.387 0.78,45.406 101.955,45.394 93.929,45.58 96.213,45.6 73.162,45.634 98.735,45.62 109.739,45.68 41.506,45.81 44.279,45.827 70.719,45.893 67.988,45.938 80.704,46.1 85.049,46.081 87.792,46.13 90.682,46.147 45.75,46.169 50.707,46.201 52.904,46.258 93.186,46.424 77.551,46.507 86.4,47.075 14.259,47.313 58.162,47.615 109.718,47.63 104.17,47.876 1.912,47.887 6.912,47.887 9.412,47.887 31.912,47.887 34.412,47.887 46.912,47.887 49.412,47.887 79.412,47.887 81.912,47.887 84.412,47.887 89.412,47.887 95.732,47.887 99.412,47.887 101.912,47.887 106.912,47.887 75.779,47.949 25.092,48.496 41.506,48.496 55.7,48.775 10.693,48.92 36.174,49.2 30.753,49.249 74.504,49.225 44.004,49.318 52.875,49.393 13.695,49.752 15.06,49.753 16.578,49.753 74.5,50.175 0.78,50.384 3.162,50.387 5.662,50.387 8.162,50.387 78.162,50.387 80.662,50.387 83.162,50.387 90.662,50.387 93.162,50.387 95.662,50.387 98.162,50.387 100.662,50.387 103.162,50.387 108.162,50.387 33.175,50.45 47.904,50.6 63.079,50.8 65.679,50.8 68.178,50.8 70.729,50.8 73.204,50.8 29.075,50.85 25.937,50.861 56.4,50.861 59.1,50.875 86.4,50.91 87.821,50.91 40.175,50.936 20.124,50.961 22.599,51.136 42.734,51.461 45.274,51.461 10.106,51.591 37.86,51.621 50.619,51.675 52.65,51.975 12.742,52.02 109.713,52.7 11.815,52.876 1.912,52.887 9.412,52.887 79.412,52.887 81.912,52.887 84.412,52.887 89.412,52.887 91.912,52.887 94.412,52.887 96.912,52.887 99.412,52.887 101.912,52.887 106.912,52.887 15.062,53.05 30.35,53.4 26.625,53.646 20.124,54.029 109.692,54.65 83.162,54.698 78.108,54.72 80.677,54.72 88.604,54.781 40.162,54.811 23.199,55.1 37.125,55.158 66.05,55.152 68.582,55.152 71.082,55.152 73.7,55.152 55.9,55.182 58.45,55.175 60.95,55.175 63.475,55.204 42.734,55.227 45.284,55.227 47.356,55.222 51.629,55.227 53.325,55.25 3.162,55.387 33.162,55.387 90.662,55.387 93.162,55.387 95.662,55.387 28.127,55.553 12.375,55.627 15.421,55.689 21.233,55.875 23.525,55.988 17.663,56.423 30.431,56.423 41.375,56.575 46.625,56.575 20.407,56.725 1.118,56.744 109.692,56.85 106.927,57.303 104.28,57.553 21.233,57.561 24.549,57.561 25.979,57.561 4.529,57.7 34.412,57.887 36.912,57.887 39.412,57.887 49.412,57.887 51.912,57.887 54.412,57.887 56.912,57.887 59.412,57.887 61.912,57.887 64.412,57.887 66.912,57.887 69.412,57.887 71.912,57.887 74.412,57.887 76.912,57.887 79.412,57.887 81.912,57.887 86.912,57.887 8.021,57.988 27.099,58.056 30.917,58.513 109.671,58.8 30.912,59.141 1.118,59.18 109.671,60.1 5.662,60.387 15.662,60.387 18.162,60.387 33.162,60.387 35.662,60.387 38.162,60.387 40.662,60.387 48.162,60.387 50.662,60.387 53.162,60.387 55.662,60.387 58.162,60.387 60.662,60.387 63.162,60.387 65.662,60.387 68.162,60.387 70.662,60.387 73.162,60.387 75.662,60.387 78.162,60.387 80.662,60.387 83.162,60.387 85.662,60.387 88.162,60.387 90.662,60.387 93.162,60.387 95.662,60.387 98.162,60.387 100.662,60.387 103.162,60.387 105.662,60.387 108.162,60.387 30.917,61.468 108.55,61.5 30.912,62.071 1.219,62.23 7.35,62.625 12.75,62.625 17.975,62.625 24.787,62.625 27.175,62.625 29.595,62.625 32.251,62.625 36.098,62.625 39.945,62.625 43.792,62.625 47.638,62.625 51.485,62.625 55.332,62.625 59.179,62.625 63.026,62.625 66.872,62.625 70.719,62.625 74.566,62.625 78.413,62.625 82.259,62.625 86.106,62.625 89.953,62.625 93.8,62.625 97.647,62.625 101.493,62.625 105.34,62.625 109.222,62.727
  other v2: 20.513,9.367 15.207,16.51 23.017,48.221 17.474,48.388 22.042,49.258 24.604,49.947
  other v3: 20.46,14.064 21.794,14.064 23.127,14.064 24.46,14.064 20.46,15.264 21.794,15.264 23.127,15.264 24.46,15.264 20.46,16.464 21.794,16.464 23.127,16.464 24.46,16.464 20.46,17.664 21.794,17.664 23.127,17.664 24.46,17.664 90.766,25.471 91.766,25.471 92.766,25.471 90.766,26.471 91.766,26.471 92.766,26.471 90.766,27.471 91.766,27.471 92.766,27.471 90.766,28.471 91.766,28.471 92.766,28.471
  other v4: 19.242,44.646 20.442,44.646 21.642,44.646 19.242,45.846 20.442,45.846 21.642,45.846 19.242,47.046 20.442,47.046 21.642,47.046
LED_PWR_CTRL: U2.A17 U10.8 | length 44.5
  Top Layer w0.125: U2.A17@22.46,19.064 22.46,19.287 22.692,19.519 22.692,22.288 22.856,22.451 26.216,22.451 26.42,22.246 v1(26.478,22.246)
  Top Layer w0.15: U10.8@22.892,47.596 23.56,47.596 23.949,47.985 v1(23.949,48.496)
  Bottom Layer w0.125: v1(23.949,48.496) 24.839,49.386 27.262,49.386 28.26,48.389 28.26,45.576 25.072,42.388 25.072,40.564 27.037,38.599 27.037,30.727 28.887,28.876 28.887,27.983 28.267,27.363 28.267,23.431 27.129,22.293 26.525,22.293 v1(26.478,22.246)
NetC6_2: C6.2 L2.2 L3.1 | length 0.9
  Top Layer w0.27: L2.2@103.058,35.73 C6.2@103.058,36.25
  Top Layer w0.3: L2.2@103.13,35.73 L3.1@103.5,35.73
NetC9_2: C9.2 L3.2 L4.1 | length 0.9
  Top Layer w0.3: L3.2@104.149,35.73 C9.2@104.635,35.73 L4.1@105.065,35.73
NetC21_1: C21.1 SB9.2 SB10.2 U9.8 | length 3.8
  Top Layer w0.25: SB9.2@86.405,23.985 86.488,23.902 ; 87.407,23.902 88.179,23.902 ; U9.8@88.99,25.06 U9.8@88.996,25.066
  Top Layer w0.3: 86.488,23.902 87.407,23.902 ; 88.179,23.902 C21.1@88.99,23.902 U9.8@88.99,25.06
NetC27_2: C27.2 C57.2 FB3.1 L8.1 TP9.1 U10.1 | length 26.5
  Top Layer w0.15: U10.1@22.892,44.096 22.892,41.619 23.024,41.486 25.072,41.486 ; C27.2@25.072,42.061 25.072,41.486 ; 25.778,41.486 25.072,41.486
  Top Layer w0.5: FB3.1@24.677,56.725 FB3.1@24.617,56.725 24.617,56.008 v1(25.05,55.575) v1(25.663,55.575)
  Bottom Layer w0.5: TP9.1@26.686,55.106 TP9.1@26.877,54.915 ; TP9.1@26.785,54.875 TP9.1@26.877,54.875
  Bottom Layer w0.8: v1(25.05,55.575) v1(25.663,55.575) 26.085,55.575 TP9.1@26.785,54.875 ; v1(26.724,41.686) v1(27.324,41.686) 29.904,44.266 29.904,51.849 26.877,54.875 TP9.1@26.877,54.915
NetC32_2: C32.2 C33.1 U2.A27 U2.G31 | length 10.1
  Top Layer w0.15: C32.2@24.953,20.385 C32.2@25.032,20.306
  Top Layer w0.2: U2.A27@24.46,19.064 24.46,19.64 24.801,19.98 C32.2@24.801,20.381 ; C32.2@24.803,20.535 24.953,20.385 C32.2@24.953,20.34 ; C32.2@25.032,20.306 v1(25.512,20.306) ; U2.G31@25.46,17.664 27.185,17.664 27.409,17.889 27.409,18.056 27.444,18.091 C33.1@27.459,18.091 27.494,18.056 27.618,18.056 v1@27.884,17.79
  Bottom Layer w0.2: v1(25.512,20.306) 25.512,20.256 25.817,19.951 27.785,19.951 28.204,19.532 28.204,18.706 27.874,18.376 27.874,17.801 v1(27.885,17.79)
NetC39_2: C39.2 U2.A15 | length 2.8
  Top Layer w0.225: U2.A15@22.06,19.064 22.06,19.42 22.286,19.646 22.286,21.619 C39.2@22.151,21.754
NetC43_1: C43.1 U2.B6 | length 3.6
  Top Layer w0.15: C43.1@18.665,20.687 19.454,20.687 20.391,19.75 20.391,18.938 ; U2.B6@20.26,18.664 20.391,18.934
  Top Layer w0.187: C43.1@18.4,20.952 C43.1@18.665,20.687
NetC44_1: C44.1 U2.A23 | length 1.1
  Top Layer w0.2: C44.1@23.55,20.154 23.55,20.139 23.66,20.029 U2.A23@23.66,19.064
NetC45_2: C45.2 U2.A13 | length 1.9
  Top Layer w0.225: U2.A13@21.66,19.064 21.66,19.644 21.77,19.754 C45.2@21.77,20.891
NetC51_1: C51.1 R32.1 U3.4 | length 2
  Top Layer w0.125: U3.4@23.549,53.836 23.739,53.646 C51.1@24.849,53.646 R32.1@25.424,53.646
NetC51_2: C51.2 Q6.2 R31.1 | length 5.3
  Top Layer w0.125: R31.1@24.849,52.595 C51.2@24.849,53.076
  Top Layer w0.4: Q6.2@20.124,53.136 20.574,53.136 21.224,52.486 24.704,52.486
NetC52_1: C52.1 R28.2 U3.3 | length 2.1
  Top Layer w0.125: U3.3@23.549,51.136 U3.3@23.59,51.095
  Top Layer w0.15: U3.3@23.549,51.136 23.549,51.086 23.774,50.861 C52.1@24.849,50.861 ; C52.1@24.839,50.861 R28.2@24.839,51.461
NetC59_1: C59.1 J3.SHLD
NetC60_1: C60.1 R3.1 U1.30 | length 1.6
  Top Layer w0.125: U1.30@101.63,35.33 102.102,35.33 102.257,35.175 102.44,35.175 C60.1@102.49,35.125 ; C60.1@102.489,35.117 102.505,35.117 102.561,35.061 102.561,34.99 102.563,34.988 102.563,34.887 R3.1@102.87,34.58
NetJ3_A5: J3.A5 U10.23 | length 27.3
  Top Layer w0.125: v1(16.132,42.343) 16.132,43.537 17.192,44.596 U10.23@17.992,44.596
  Top Layer w0.15: J3.A5@7.485,25.384 v1@8.526,25.384
  Bottom Layer w0.125: v1(8.527,25.383) 8.527,25.451 8.72,25.644 8.72,26.62 9.825,27.725 14.019,27.725 16.361,30.067 16.361,41.429 16.132,41.657 v1(16.132,42.343)
NetJ3_B5: J3.B5 U10.24 | length 29.6
  Top Layer w0.125: v1(16.679,41.886) 16.679,43.523 17.252,44.096 U10.24@17.992,44.096
  Top Layer w0.15: J3.B5@7.485,22.384 v1(8.529,22.384)
  Bottom Layer w0.125: v1(8.529,22.384) 8.538,22.384 9,22.846 9,26.495 9.952,27.447 14.147,27.447 16.679,29.979 v1(16.679,41.886)
NetL2_1: L2.1 U1.31 | length 0.9
  Top Layer w0.2: U1.31@101.664,35.73 L2.1@102.521,35.73 ; L2.1@102.521,35.73 L2.1@102.522,35.729
NetL8_2: L8.2 U10.3 | length 4.2
  Top Layer w0.3: U10.3@22.892,45.096 23.492,45.096 24.292,44.296 L8.2@26.749,44.296
NetL9_2: L9.2 U10.5 | length 3.8
  Top Layer w0.3: U10.5@22.892,46.096 23.167,46.096 23.537,46.096 24.337,46.896 26.332,46.896 L9.2@26.357,46.871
